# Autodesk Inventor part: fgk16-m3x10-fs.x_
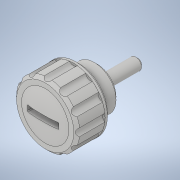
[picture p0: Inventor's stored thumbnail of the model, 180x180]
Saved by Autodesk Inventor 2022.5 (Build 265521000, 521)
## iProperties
Created: 2021-08
Part Number: fgk16-m3x10-fs.x_
Material: 一般
Document SubType Name: Modeling
Designer: ImaoCorp
Density: 1 g/cm^3
Appearance: 既定
Sending System: SOLIDWORKS 2019-2019304
MC: AMD64
MC_MODEL: Intel64 Family 6 Model 60 Stepping 3, GenuineIntel
OS: Windows_NT
FRU: Parasolid Version 31.0, build 290,  9- 1-2019
FORMAT: text
GUISE: transmit
KEY: fgk16-m3x10-fs
FILE: fgk16-m3x10-fs.x_t
DATE: Wed Aug 11 15:02:35 2021
Author: ImaoCorp
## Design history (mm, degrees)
feature "Base1"
node "ソリッド1"
